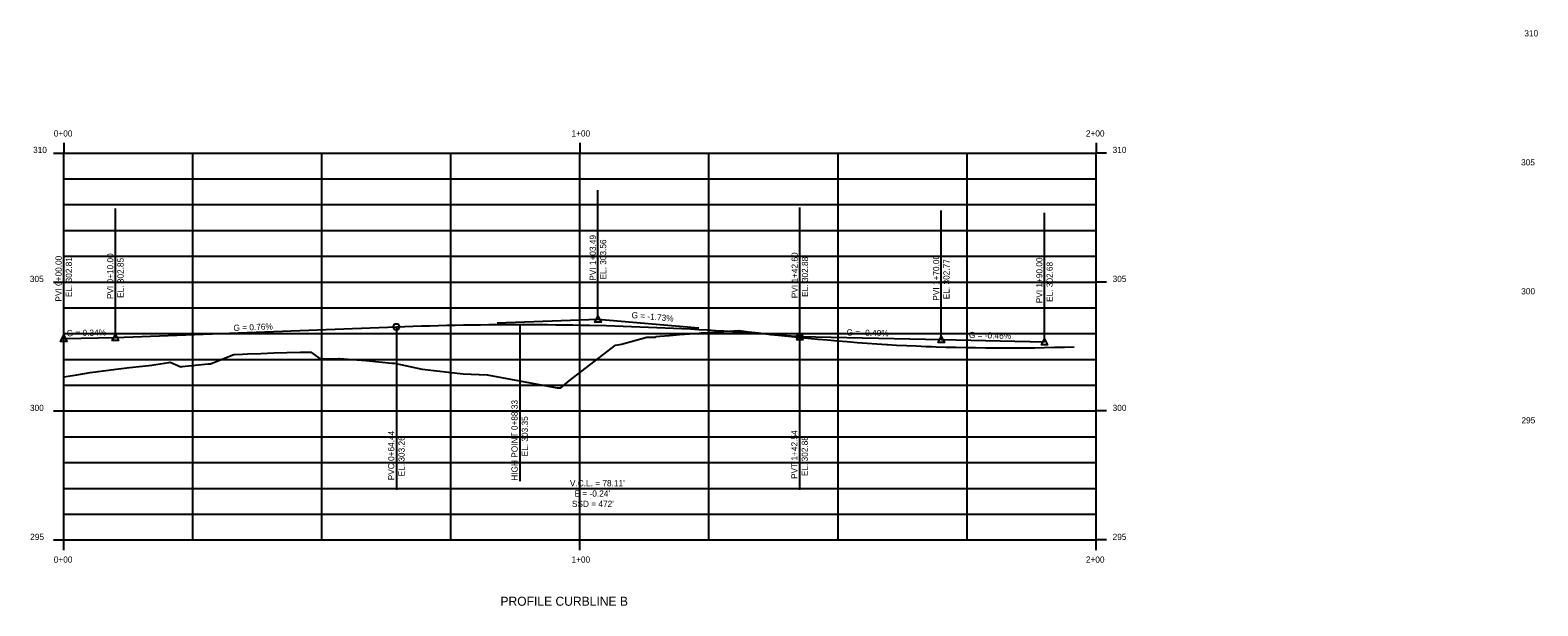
# Model space of a CAD drawing. Extents: x 916627 to 921213, y 329780 to 330157.
# Drawn here: x 920275.9 to 920568, y 329790.9 to 329902.5 of the extents above; entities that cross this region are included whole.
import ezdxf

# ---------------------------------------------------------------- set-up
doc = ezdxf.new("R2010")
doc.units = 0
for name, color, linetype in [('D_Roadway_Centerline', 7, 'Continuous'), ('D_Roadway_Centerline_Bearings', 7, 'Continuous'), ('D_Roadway_Centerline_CurveData', 7, 'Continuous'), ('D_Roadway_Centerline_Text', 7, 'Continuous')]:
    doc.layers.add(name, color=color, linetype=linetype)

msp = doc.modelspace()

# ---------------------------------------------------------------- linework, layer by layer
at = {"layer": 'D_Roadway_Centerline'}
for p, q in [((920282.41, 329880.68), (920282.41, 329878.68)), ((920382.41, 329880.68), (920382.41, 329878.68)), ((920482.41, 329880.68), (920482.41, 329878.68)), ((920280.41, 329878.68), (920282.41, 329878.68)), ((920280.41, 329878.68), (920282.41, 329878.68)), ((920282.41, 329878.68), (920482.41, 329878.68)), ((920282.41, 329803.68), (920282.41, 329878.68)), ((920382.41, 329803.68), (920382.41, 329878.68)), ((920482.41, 329803.68), (920482.41, 329878.68)), ((920484.41, 329878.68), (920482.41, 329878.68)), ((920484.41, 329878.68), (920482.41, 329878.68)), ((920280.41, 329853.68), (920282.41, 329853.68)), ((920282.41, 329853.68), (920482.41, 329853.68)), ((920484.41, 329853.68), (920482.41, 329853.68)), ((920282.41, 329842.75), (920292.41, 329842.92)), ((920292.41, 329842.92), (920346.85, 329844.99)), ((920424.96, 329843.1), (920425.01, 329843.1)), ((920425.01, 329843.1), (920452.41, 329842.55)), ((920452.41, 329842.55), (920472.41, 329842.09)), ((920280.41, 329828.68), (920282.41, 329828.68)), ((920282.41, 329828.68), (920482.41, 329828.68)), ((920484.41, 329828.68), (920482.41, 329828.68)), ((920280.41, 329803.68), (920282.41, 329803.68)), ((920282.41, 329803.68), (920482.41, 329803.68)), ((920282.41, 329801.68), (920282.41, 329803.68)), ((920382.41, 329801.68), (920382.41, 329803.68)), ((920484.41, 329803.68), (920482.41, 329803.68)), ((920482.41, 329801.68), (920482.41, 329803.68))]:
    msp.add_line(p, q, dxfattribs=at)
msp.add_lwpolyline([(920346.85, 329844.99), (920348.48, 329845.05), (920350.1, 329845.11), (920351.73, 329845.16), (920353.36, 329845.21), (920354.98, 329845.25), (920356.61, 329845.29), (920358.24, 329845.33), (920359.87, 329845.36), (920361.49, 329845.38), (920363.12, 329845.4), (920364.75, 329845.42), (920366.38, 329845.43), (920368, 329845.44), (920369.63, 329845.45), (920371.26, 329845.45), (920372.88, 329845.45), (920374.51, 329845.44), (920376.14, 329845.43), (920377.77, 329845.41), (920379.39, 329845.39), (920381.02, 329845.37), (920382.65, 329845.34), (920384.28, 329845.3), (920387.53, 329845.23), (920389.16, 329845.18), (920390.79, 329845.13), (920392.41, 329845.08), (920394.04, 329845.02), (920395.67, 329844.95), (920397.29, 329844.89), (920398.92, 329844.82), (920400.55, 329844.74), (920402.18, 329844.66), (920403.8, 329844.58), (920405.43, 329844.49), (920407.06, 329844.4), (920408.69, 329844.3), (920410.31, 329844.2), (920411.94, 329844.1), (920413.57, 329843.99), (920415.19, 329843.87), (920416.82, 329843.76), (920418.45, 329843.63), (920420.08, 329843.51), (920421.7, 329843.38), (920423.33, 329843.24), (920424.96, 329843.1)], dxfattribs=at)
at = {"layer": 'D_Roadway_Centerline_Bearings'}
msp.add_lwpolyline([(920282.41, 329835.29), (920284.96, 329835.72), (920287.5, 329836.11), (920289.08, 329836.34), (920290.04, 329836.47), (920292.59, 329836.8), (920295.13, 329837.09), (920297.67, 329837.36), (920299.47, 329837.53), (920300.22, 329837.66), (920302.76, 329838.08), (920303.04, 329838.13), (920305.11, 329837.22), (920305.28, 329837.28), (920305.3, 329837.28), (920307.85, 329837.57), (920310.39, 329837.81), (920310.82, 329837.85), (920312.93, 329838.68), (920315.33, 329839.61), (920315.48, 329839.62), (920317.02, 329839.68), (920318.02, 329839.73), (920320.56, 329839.84), (920323.11, 329839.93), (920325.65, 329840), (920328.19, 329840.05), (920330.26, 329840.08), (920330.74, 329839.74), (920332.07, 329838.78), (920333.28, 329838.78), (920334.94, 329838.76), (920335.63, 329838.83), (920335.82, 329838.83), (920338.37, 329838.66), (920340.91, 329838.47), (920343.45, 329838.24), (920346, 329837.98), (920346.43, 329837.93), (920348.54, 329837.5), (920351.86, 329836.79), (920359.81, 329835.86), (920364.45, 329835.67), (920377.98, 329833.17), (920378.48, 329833.18), (920378.71, 329833.2), (920380.35, 329834.5), (920389.29, 329841.42), (920389.69, 329841.5), (920390.45, 329841.66), (920395.35, 329842.97), (920397.08, 329843.01), (920397.22, 329843.12), (920397.88, 329843.18), (920399.79, 329843.34), (920401.71, 329843.49), (920403.62, 329843.64), (920405.53, 329843.78), (920405.89, 329843.81), (920407.44, 329843.91), (920409.35, 329844.04), (920411.26, 329844.15), (920413.18, 329844.26), (920413.25, 329844.26), (920415.09, 329844.04), (920417, 329843.8), (920418.91, 329843.58), (920419.33, 329843.53), (920420.82, 329843.37), (920422.73, 329843.17), (920424.64, 329842.98), (920426.56, 329842.79), (920428.47, 329842.61), (920430.38, 329842.44), (920432.29, 329842.28), (920434.2, 329842.12), (920436.11, 329841.98), (920438.03, 329841.84), (920439.94, 329841.7), (920441.85, 329841.58), (920442.02, 329841.57), (920443.76, 329841.47), (920445.67, 329841.37), (920447.58, 329841.28), (920449.49, 329841.19), (920450.55, 329841.15), (920451.41, 329841.12), (920453.32, 329841.07), (920455.23, 329841.02), (920457.14, 329840.99), (920458.77, 329840.96), (920459.05, 329840.96), (920460.96, 329840.93), (920462.87, 329840.92), (920464.79, 329840.92), (920466.7, 329840.92), (920468.61, 329840.93), (920470.52, 329840.95), (920472.43, 329840.98), (920474.34, 329841.02), (920476.26, 329841.07), (920478.17, 329841.13)], dxfattribs=at)
at = {"layer": 'D_Roadway_Centerline_CurveData'}
for p, q in [((920385.9, 329846.48), (920385.9, 329871.48)), ((920282.41, 329842.75), (920282.41, 329867.75)), ((920292.41, 329842.92), (920292.41, 329867.92)), ((920425.01, 329843.1), (920425.01, 329868.1)), ((920452.41, 329842.55), (920452.41, 329867.55)), ((920472.41, 329842.09), (920472.41, 329867.09)), ((920366.38, 329845.74), (920385.9, 329846.48)), ((920385.9, 329846.48), (920405.43, 329844.79)), ((920346.85, 329844.99), (920346.85, 329819.99)), ((920346.85, 329844.99), (920346.85, 329813.37)), ((920370.74, 329845.45), (920370.74, 329815.07)), ((920424.96, 329843.1), (920424.96, 329818.1)), ((920424.96, 329818.1), (920424.96, 329813.37))]:
    msp.add_line(p, q, dxfattribs=at)
for points in [[(920385.9, 329847.08), (920386.5, 329845.88), (920385.3, 329845.88)], [(920282.41, 329843.35), (920283.01, 329842.15), (920281.81, 329842.15)], [(920292.41, 329843.52), (920293.01, 329842.32), (920291.81, 329842.32)], [(920425.01, 329843.7), (920425.61, 329842.5), (920424.41, 329842.5)], [(920452.41, 329843.15), (920453.01, 329841.95), (920451.81, 329841.95)], [(920472.41, 329842.69), (920473.01, 329841.49), (920471.81, 329841.49)]]:
    msp.add_lwpolyline(points, close=True, dxfattribs=at)
msp.add_lwpolyline([(920346.85, 329813.68), (920424.96, 329813.68)], dxfattribs=at)
for centre in [(920346.85, 329844.99), (920424.96, 329843.1)]:
    msp.add_circle(centre, 0.6, dxfattribs=at)
at = {"layer": 'D_Roadway_Centerline_Text'}
for p, q in [((920307.41, 329803.68), (920307.41, 329878.68)), ((920332.41, 329803.68), (920332.41, 329878.68)), ((920357.41, 329803.68), (920357.41, 329878.68)), ((920407.41, 329803.68), (920407.41, 329878.68)), ((920432.41, 329803.68), (920432.41, 329878.68)), ((920457.41, 329803.68), (920457.41, 329878.68)), ((920282.41, 329873.68), (920482.41, 329873.68)), ((920282.41, 329868.68), (920482.41, 329868.68)), ((920282.41, 329863.68), (920482.41, 329863.68)), ((920282.41, 329858.68), (920482.41, 329858.68)), ((920282.41, 329848.68), (920482.41, 329848.68)), ((920282.41, 329843.68), (920482.41, 329843.68)), ((920282.41, 329838.68), (920482.41, 329838.68)), ((920282.41, 329833.68), (920482.41, 329833.68)), ((920282.41, 329823.68), (920482.41, 329823.68)), ((920282.41, 329818.68), (920482.41, 329818.68)), ((920282.41, 329813.68), (920482.41, 329813.68)), ((920282.41, 329808.68), (920482.41, 329808.68))]:
    msp.add_line(p, q, dxfattribs=at)

# ---------------------------------------------------------------- texts
at = {"layer": 'D_Roadway_Centerline'}
for s, p in [('HIGH POINT 0+88.33', (920370.34, 329815.16)), ('EL. 303.35', (920372.34, 329819.89))]:
    msp.add_text(s, height=1.2, rotation=90, dxfattribs=at).set_placement(p)
at = {"layer": 'D_Roadway_Centerline_CurveData'}
for s, height, p in [('310', 1.2, (920565.37, 329901.28)), ('310', 1.2, (920565.37, 329901.28)), ('0+00', 1.2, (920280.48, 329881.88)), ('1+00', 1.2, (920380.78, 329881.88)), ('2+00', 1.2, (920480.43, 329881.88)), ('310', 1.2, (920276.47, 329878.68)), ('310', 1.2, (920276.47, 329878.68)), ('310', 1.2, (920485.61, 329878.68)), ('310', 1.2, (920485.61, 329878.68)), ('305', 1.2, (920564.74, 329876.28)), ('305', 1.2, (920275.84, 329853.68)), ('305', 1.2, (920485.61, 329853.68)), ('300', 1.2, (920564.77, 329851.28)), ('300', 1.2, (920275.87, 329828.68)), ('300', 1.2, (920485.61, 329828.68)), ('295', 1.2, (920564.81, 329826.28)), ("V.C.L. = 78.11'", 1.2, (920380.47, 329814.08)), ("SSD = 472'", 1.2, (920380.86, 329810.08)), ("E = -0.24'", 1.2, (920381.37, 329812.08)), ('295', 1.2, (920275.91, 329803.68)), ('295', 1.2, (920485.61, 329803.68)), ('0+00', 1.2, (920280.48, 329799.28)), ('1+00', 1.2, (920380.78, 329799.28)), ('2+00', 1.2, (920480.43, 329799.28)), ('PROFILE CURBLINE B', 1.75, (920367.01, 329790.93))]:
    msp.add_text(s, height=height, dxfattribs=at).set_placement(p)
for s, rotation, p in [('PVI 1+03.49', 90, (920385.5, 329853.92)), ('EL. 303.56', 90, (920387.5, 329854.17)), ('PVI 0+00.00', 90, (920282.01, 329849.89)), ('EL. 302.81', 90, (920284.01, 329850.74)), ('PVI 0+10.00', 90, (920292.01, 329850.36)), ('EL. 302.85', 90, (920294.01, 329850.6)), ('PVI 1+42.60', 90, (920424.61, 329850.54)), ('EL. 302.88', 90, (920426.61, 329850.8)), ('PVI 1+70.00', 90, (920452.01, 329850.05)), ('EL. 302.77', 90, (920454.01, 329850.35)), ('PVI 1+90.00', 90, (920472.01, 329849.56)), ('EL. 302.68', 90, (920474.01, 329849.82)), ('G = 0.76%', 2.1847, (920315.31, 329844.19)), ('G = -1.73%', 355.053, (920392.37, 329846.7)), ('G = 0.34%', 0.9813, (920282.99, 329843.16)), ('G = -0.40%', 358.8538, (920434.04, 329843.32)), ('G = -0.46%', 358.6905, (920457.76, 329842.83)), ('PVC 0+64.44', 90, (920346.45, 329815.25)), ('EL. 303.26', 90, (920348.45, 329816.01)), ('PVT 1+42.54', 90, (920424.56, 329815.51)), ('EL. 302.88', 90, (920426.56, 329816.05))]:
    msp.add_text(s, height=1.2, rotation=rotation, dxfattribs=at).set_placement(p)

doc.saveas('drawing.dxf')
